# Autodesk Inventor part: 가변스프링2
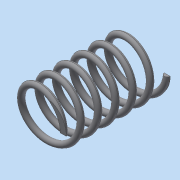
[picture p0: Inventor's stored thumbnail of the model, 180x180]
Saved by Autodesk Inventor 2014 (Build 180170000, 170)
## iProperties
Created: 2023-01
Part Number: 가변스프링2
Material: 일반
Document SubType Name: Modeling
Designer: dg
Density: 1 g/cm^3
Appearance: 기본값
Mass: 0.981303 g
Surface Area: 20.018 cm^2
Volume: 0.981303 cm^3
Author: dg
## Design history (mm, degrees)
sketch "스케치1"
  geometry: L1 (8.5, 0)-(0, 0); L2 (0, 0)-(0, 17); L3 (0, 17)-(8.5, 17); C1 r 1 at (8.5, 0)
  constraints: 6 end point, 1 centre point, 1 coincident, 1 horizontal, 1 parallel, 1 vertical, 1 vertical alignment
  dimensions: "d0" = 2 diameter of C1; "d1" = 17 distance of L1.end L2.end (derived); "d2" = 17 diameter of L1.start L2
feature "코일1" sketch "스케치1" pitch "d3" = 10; turns "d5" = 6; dims "d4" = 17 (= d1), "d6" = 0, angle "d7" = 90 deg, angle "d8" = 90 deg, "d9" = 0, "d10" = 0
node "작업 평면1"
node "작업 평면2"
feature "분할1"
feature "분할2"
node "솔리드1"
other parameters: "d11" = 90 deg, "d12" = 90 deg
